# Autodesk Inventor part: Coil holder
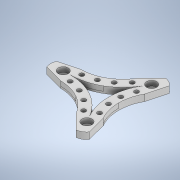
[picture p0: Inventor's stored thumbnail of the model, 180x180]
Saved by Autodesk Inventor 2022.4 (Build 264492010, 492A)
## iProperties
Created: 2023-09
Part Number: Coil holder
Material: Generic
Document SubType Name: Modeling
Designer: tmass
Density: 1 g/cm^3
Appearance: Default
Author: tmass
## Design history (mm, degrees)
derived "Fidget_bottom_3cm.ipt"
sketch "Sketch1"
  geometry: L1 (8.106, -10.67)-(-12.36, -5.175); L2 (-15.542, 0)-(79.177, 0); L3 (8.106, 10.67)-(-12.36, 5.175); L4 (65.181, -22.282)-(70.655, -42.754); L5 (46.699, -32.952)-(61.691, -47.929); L6 (46.699, 32.952)-(61.691, 47.929); L7 (65.181, 22.282)-(70.655, 42.754); A1 r 45.5 centre (7.567, -56.167) between (30.317, -16.763) and (8.106, -10.67) reference; A2 r 13.4 centre (0, 0) between (8.106, 10.67) and (8.106, -10.67) reference; A3 r 13.4 centre (59.993, -34.637) between (46.699, -32.952) and (65.181, -22.282) reference; A4 r 13.4 centre (59.993, 34.637) between (65.181, 22.282) and (46.699, 32.952) reference; A5 r 45.5 centre (7.567, 56.167) between (30.317, 16.763) and (46.699, 32.952) reference; A6 r 45.5 centre (7.567, 56.167) between (8.106, 10.67) and (30.317, 16.763) reference; A7 r 45.5 centre (7.567, -56.167) between (46.699, -32.952) and (30.317, -16.763) reference; A8 r 45.5 centre (104.852, 0) between (65.181, 22.282) and (59.352, 0) reference; A9 r 45.5 centre (104.852, 0) between (59.352, 0) and (65.181, -22.282) reference; 2 further points
  constraints: 14 end point, 1 horizontal, 1 point on circle, 1 symmetric about line, 19 other
  dimensions: "d3" = 360 deg dimension on point (39.995, 0) L1.start (derived)
extrude "Extrusion1" cut sketch "Sketch1" distance "d5" = 10; taper "d6" = 0 deg
feature "Solid4::Fidget_bottom_3cm.ipt" dims "d0" = 10
tag "TaggingFeature1"
body "Solid1"
